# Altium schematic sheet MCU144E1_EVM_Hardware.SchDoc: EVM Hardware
size 431 x 279 mm; Date: Not shown in title block; ApprovedBy: Not shown in title block; CheckedBy: Not shown in title block; Author: Not shown in title block; CompanyName: Not shown in title block; DrawnBy: Gustavo Martinez; Engineer: Not shown in title block; Organization: Not shown in title block; Address1: Not shown in title block; Address2: Not shown in title block; Address3: Not shown in title block; Address4: Not shown in title block; DocumentNumber: 11; Revision: Use project parameter SCH_Rev; SheetNumber: 8; SheetTotal: 8; PageSetup: Record=PageOptions¦CenterHorizontal=True¦CenterVertical=True¦PrintScale=1.00¦XCorrection=1.00¦YCorrection=1.00¦PrintKind=0¦BorderSize=5000000¦LeftOffset=0¦BottomOffset=0¦Orientation=2¦PaperLength=1000¦PaperWidth=1000¦Scale=100¦PaperSource=15¦PrintQuality=600¦MediaType=1¦DitherType=10¦PaperKind=Letter¦PrintScaleMode=1
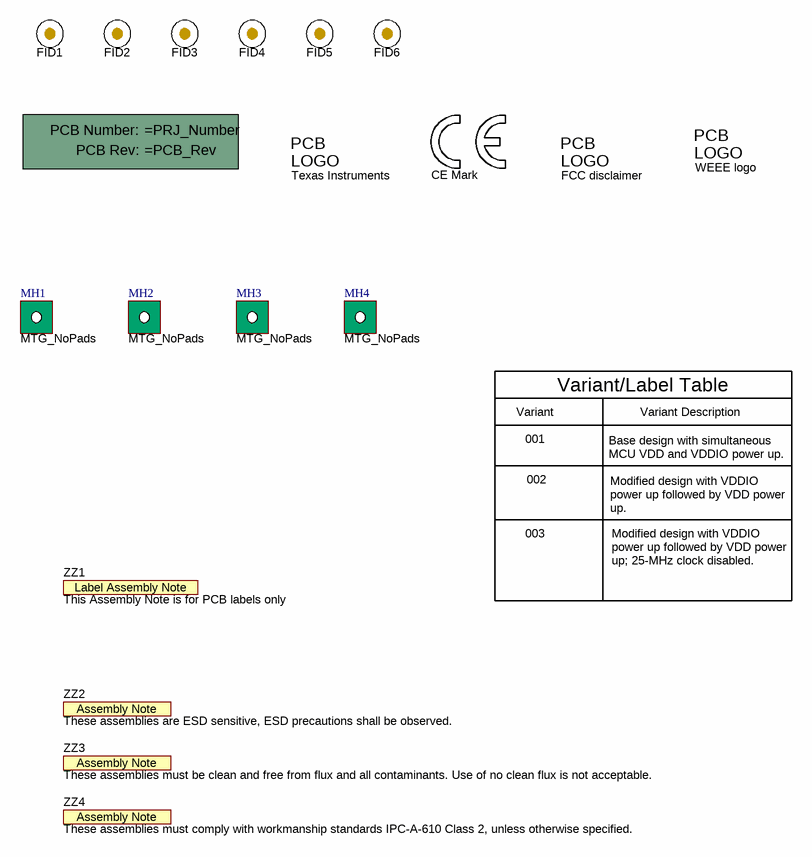
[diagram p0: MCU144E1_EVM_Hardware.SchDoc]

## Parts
!PCB1  Printed Circuit Board  (value not drawn)  (mechanical)
FID1  Fiducial  [Fiducial10-20]  (value not drawn)  (no BOM)
FID2  Fiducial  [Fiducial10-20]  (value not drawn)  (no BOM)
FID3  Fiducial  [Fiducial10-20]  (value not drawn)  (no BOM)
FID4  Fiducial  [Fiducial10-20]  (value not drawn)  (no BOM)
FID5  Fiducial  [Fiducial10-20]  (value not drawn)  (no BOM)
FID6  Fiducial  [Fiducial10-20]  (value not drawn)  (no BOM)
Logo1  CE Mark  [CE_Mark_5mm]  (no BOM)
Logo2  Texas Instruments  [TI_Stacked_Overlay_Small]  (no BOM)
Logo3  FCC disclaimer  [FCC_disclaimer]  (no BOM)
Logo4  WEEE logo  [WEEE_Minimum]  (no BOM)
MH1  MTG_NoPads  [MTG_159mil]  (no BOM)
MH2  MTG_NoPads  [MTG_159mil]  (no BOM)
MH3  MTG_NoPads  [MTG_159mil]  (no BOM)
MH4  MTG_NoPads  [MTG_159mil]  (no BOM)
ZZ1  This Assembly Note is for PCB labels only  [AssemblyNoteLabel]  (no BOM)
ZZ2  These assemblies are ESD sensitive, ESD precautions shall be observed.  [AssemblyNote]  (no BOM)
ZZ3  These assemblies must be clean and free from flux and all contaminants. Use of no clean flux is not acceptable.  [AssemblyNote]  (no BOM)
ZZ4  These assemblies must comply with workmanship standards IPC-A-610 Class 2, unless otherwise specified.  [AssemblyNote]  (no BOM)

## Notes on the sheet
- Variant
- 001
- Variant/Label Table
- Variant Description
- 002
- Base design with simultaneous MCU VDD and VDDIO power up.
- 003
- Modified design with VDDIO power up followed by VDD power up.
- Modified design with VDDIO power up followed by VDD power up; 25-MHz clock disabled.

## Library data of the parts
!PCB1 = CMP-0003618-2: Manufacturer: Any
FID1-FID6 = CMP-0077181-1: Fiducial mark.  There is nothing to buy or mount.
Logo1 = CMP-0074844-1: SymbolCreator: a0412235
Logo2 = CMP-0074838-1: Texas Instrument Corporate Signature; SymbolCreator: a0412235; Lib Reference: TI_Logo; Library Reference: Logo
Logo3 = CMP-0074847-1: FCC_disclaimer
Logo4 = CMP-0074769-3: Manufacturer: Texas Instruments; AEC Category: Q200; CompType: IC
MH1-MH4 = CMP-0078424-2: PCB Mounting Hole, No Pad; Manufacturer: Any; Key: Mounting Hole (non-standard) No Pad
ZZ1 = CMP-0003616-3
ZZ2 = CMP-0077236-1
ZZ3 = CMP-0077237-1
ZZ4 = CMP-0077238-1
